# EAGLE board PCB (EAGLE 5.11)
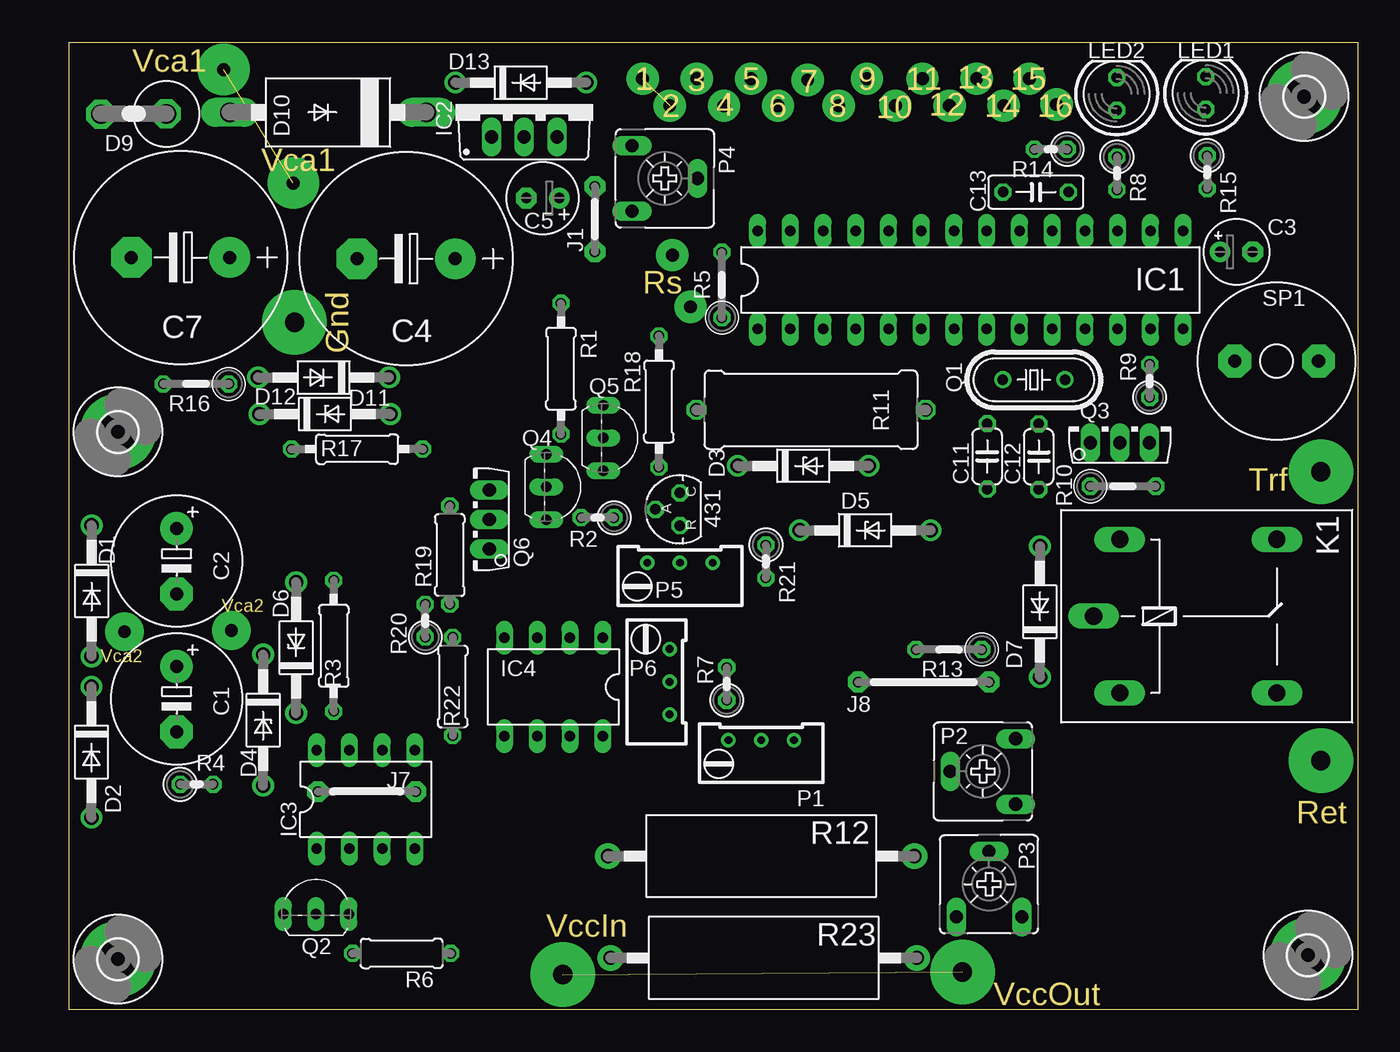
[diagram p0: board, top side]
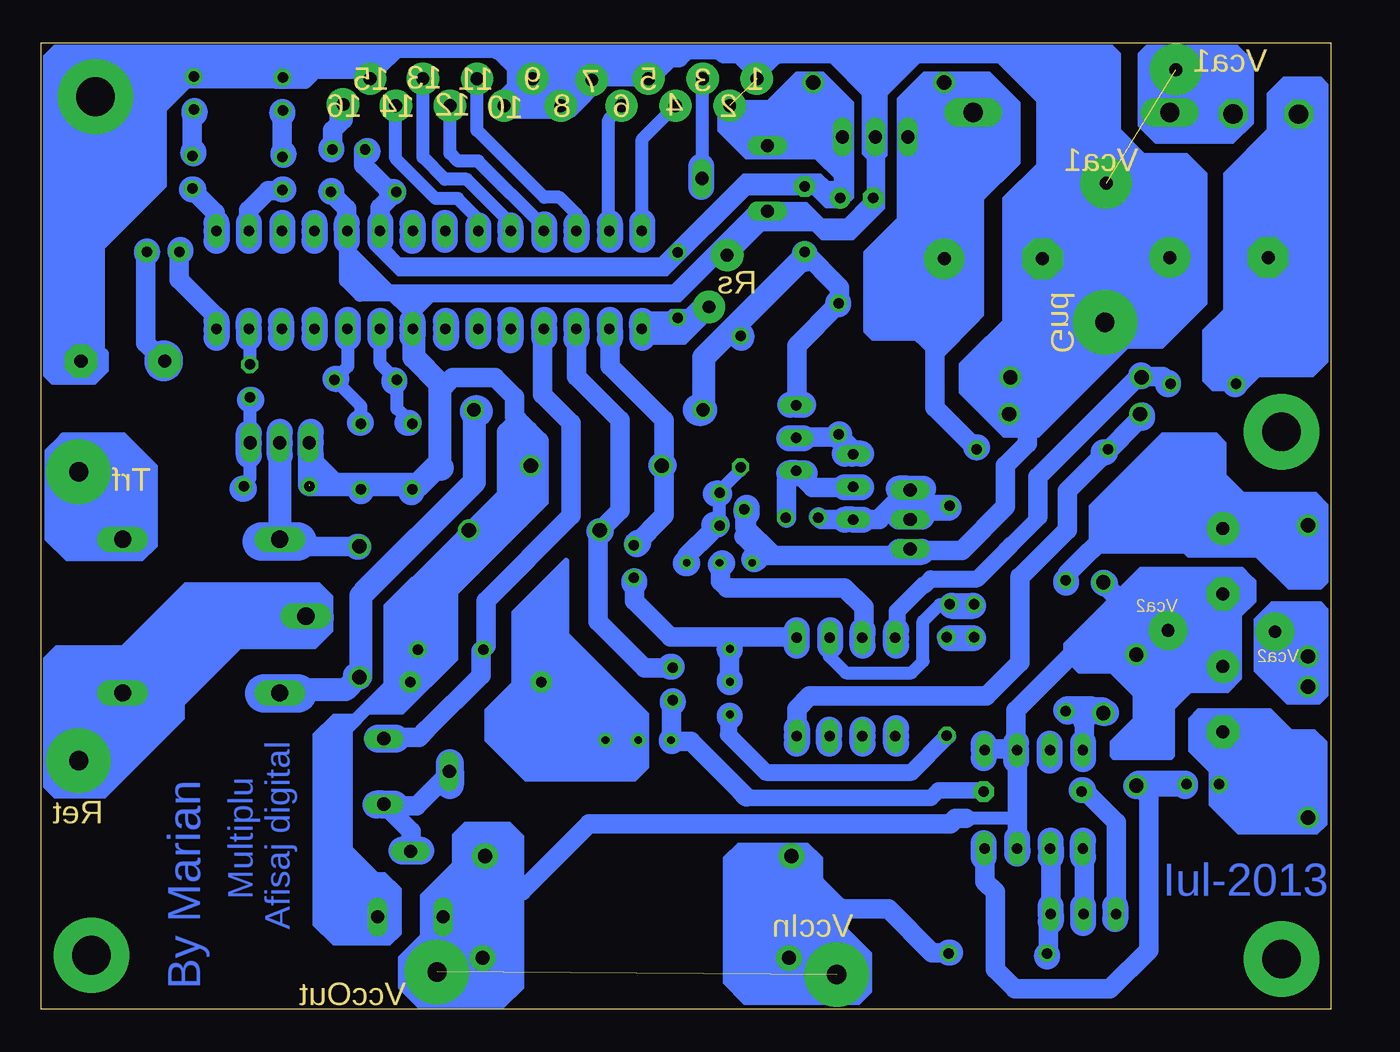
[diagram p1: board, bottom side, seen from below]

Size 100 x 75 mm. Coordinates in mm from the lower left corner, seen from the top.
Outline: 0,0 100,0 100,75 0,75 0,0
Copper layers (1*16): Top 0.035mm / dielectric 1.5mm / Bottom 0.035mm
Design rules "default": minimum track width 10mil, minimum drill 24mil, track to track 8mil, track to pad 8mil, pad to pad 8mil, via to via 8mil, smd to smd 8mil, copper to edge 40mil, drill to drill 8mil, minimum pad ring 10mil, minimum via ring 8mil, stop-mask expansion 4mil, vias tented up to drill 0mil, thermal gap 10mil

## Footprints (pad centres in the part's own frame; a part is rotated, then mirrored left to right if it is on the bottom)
TO92-CLP = drill 0.813 octagon: A 0,1.905; C 1.27,0; R -1.27,0
E5-10,5 = drill 1.016 pad 2.54 round: + -2.54,0 | drill 1.016 pad 2.54 octagon: - 2.54,0
E2,5-5 = drill 0.813 pad 1.6 round: + -1.27,0 | drill 0.813 pad 1.6 octagon: - 1.27,0
E7,5-16 = drill 1.016 pad 3.15 round: + -3.81,0 | drill 1.016 pad 3.15 octagon: - 3.81,0
E2,5-6 = drill 0.813 pad 1.6 round: + -1.27,0 | drill 0.813 pad 1.6 octagon: - 1.27,0
C050-024X044 = drill 0.813 octagon: 1 -2.54,0; 2 2.54,0
C050-025X075 = drill 0.813 octagon: 1 -2.54,0; 2 2.54,0
DO41-10 = drill 1.118 round: A 5.08,0; C -5.08,0
DO41Z10 = drill 1.118 round: A 5.08,0; C -5.08,0
RAD5G = drill 1.499 octagon: A 2.54,0.025; C -2.54,0
C2673 = drill 1.499 long: A 7.62,0; C -7.62,0
3,0-PAD = drill 3 pad 5.842 round: B3,0 0,0
DIL28-3 = drill 0.813 long: 1 -16.51,-3.81; 2 -13.97,-3.81; 3 -11.43,-3.81; 4 -8.89,-3.81; 5 -6.35,-3.81; 6 -3.81,-3.81; 7 -1.27,-3.81; 8 1.27,-3.81; 9 3.81,-3.81; 10 6.35,-3.81; 11 8.89,-3.81; 12 11.43,-3.81; 13 13.97,-3.81; 14 16.51,-3.81; 15 16.51,3.81; 16 13.97,3.81; 17 11.43,3.81; 18 8.89,3.81; 19 6.35,3.81; 20 3.81,3.81; 21 1.27,3.81; 22 -1.27,3.81; 23 -3.81,3.81; 24 -6.35,3.81; 25 -8.89,3.81; 26 -11.43,3.81; 27 -13.97,3.81; 28 -16.51,3.81
TO220BV = drill 1.016 long: D 0,-2.54; G -2.54,-2.54; S 2.54,-2.54
DIL08 = drill 0.813 long: 1 -3.81,-3.81; 2 -1.27,-3.81; 3 1.27,-3.81; 4 3.81,-3.81; 5 3.81,3.81; 6 1.27,3.81; 7 -1.27,3.81; 8 -3.81,3.81
05 = drill 0.813 pad 1.6 octagon: 1 -2.54,0; 2 2.54,0
07 = drill 0.813 pad 1.6 octagon: 1 -3.81,0; 2 3.81,0
10 = drill 0.813 pad 1.6 octagon: 1 -5.08,0; 2 5.08,0
G5LE = drill 1.321 long: 1 -7.493,-5.969; 2 -7.493,5.969; O 4.699,5.969; P -9.525,0; S 4.699,-5.969
LED5MM = drill 0.813 octagon: A -1.27,0; K 1.27,0
RTRIM64W = drill 0.61 round: 1 1.27,-2.54; 2 1.27,0; 3 1.27,2.54
CA6V = drill 1.016 long: A -2.54,-2.54; E 2.54,-2.54; S 0,2.54
HC49/S = drill 0.813 round: 1 -2.413,0; 2 2.413,0
TO92-EBC = drill 0.813 long: B 0,-1.27; C -2.54,-1.27; E 2.54,-1.27
TO126BV = drill 1.016 long: 1 -2.286,-1.27; 2 0,-1.27; 3 2.286,-1.27
0207/10 = drill 0.813 octagon: 1 -5.08,0; 2 5.08,0
0207/2V = drill 0.813 octagon: 1 -1.27,0; 2 1.27,0
0207/5V = drill 0.813 octagon: 1 -2.54,0; 2 2.54,0
0207/7 = drill 0.813 octagon: 1 -3.81,0; 2 3.81,0
0617/17 = drill 1.016 octagon: 1 -8.89,0; 2 8.89,0
RWM6X22 = drill 1.1 pad 2 round: 1 -11.89,0; 2 11.89,0
AL60P = drill 1.016 pad 2.54 octagon: 1 -3.251,0; 2 3.251,0

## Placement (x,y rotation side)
431  [TO92-CLP]  47.39,38.79 90 top
C1  220u  [E5-10,5]  8.34,24.07 270 top
C2  220u  [E5-10,5]  8.34,34.77 270 top
C3  10u  [E2,5-5]  90.55,58.77 0 top
C4  2.2m  [E7,5-16]  26.15,58.23 180 top
C5  47u  [E2,5-6]  36.75,62.93 180 top
C7  2.2m  [E7,5-16]  8.65,58.33 180 top
C11  [C050-024X044]  71.22,42.89 90 top
C12  [C050-024X044]  75.22,42.87 90 top
C13  [C050-025X075]  74.99,63.4 0 top
D1  [DO41-10]  1.76,32.46 270 top
D2  [DO41-10]  1.74,19.96 270 top
D3  [DO41Z10]  56.95,42.16 0 top
D4  [DO41Z10]  15.06,22.45 270 top
D5  5v1  [DO41Z10]  61.75,37.16 0 top
D6  [DO41Z10]  17.62,28.05 90 top
D7  1N4007  [DO41-10]  75.31,30.84 90 top
D9  [RAD5G]  5.01,69.47 180 top
D10  [C2673]  20.09,69.58 180 top
D11  [DO41Z10]  19.85,46.18 0 top
D12  [DO41Z10]  19.75,49.02 180 top
D13  [DO41-10]  35.04,71.89 0 top
E$1  [3,0-PAD]  95.8,70.8 0 top
E$2  [3,0-PAD]  3.8,3.9 0 top
E$3  [3,0-PAD]  96.1,4.2 0 top
E$4  [3,0-PAD]  3.8,44.8 0 top
IC1  PIC16876P  [DIL28-3]  69.92,56.59 0 top
IC2  [TO220BV]  35.31,70.22 0 top
IC3  LM358  [DIL08]  23.02,16.29 0 top
IC4  LM358  [DIL08]  37.58,25.01 180 top
J1  [05]  40.8,61.3 90 top
J7  [07]  23.1,16.9 180 top
J8  [10]  66.3,25.4 0 top
K1  3V  [G5LE]  89,30.5 0 top
LED1  [LED5MM]  88.17,71.08 90 top
LED2  [LED5MM]  81.27,71.02 90 top
P1  5k  [RTRIM64W]  53.69,19.62 90 top
P2  10k  [CA6V]  70.89,18.46 90 top
P3  10k  [CA6V]  71.36,9.71 0 top
P4  10k  [CA6V]  46.21,64.46 270 top
P5  5k  [RTRIM64W]  47.39,33.38 90 top
P6  100k  [RTRIM64W]  45.32,25.41 0 top
Q1  [HC49/S]  74.84,48.84 0 top
Q2  [TO92-EBC]  19.17,8.68 0 top
Q3  [TO126BV]  81.51,45.22 0 top
Q4  [TO92-EBC]  38.3,40.53 270 top
Q5  [TO92-EBC]  42.72,44.33 270 top
Q6  [TO126BV]  31.33,38.01 90 top
R1  1k  [0207/10]  38.16,49.7 270 top
R2  [0207/2V]  41,38.14 180 top
R3  [0207/10]  20.54,28.2 90 top
R4  [0207/2V]  9.9,17.46 0 top
R5  [0207/5V]  50.64,56.2 90 top
R6  100  [0207/7]  25.8,4.34 180 top
R7  470  [0207/2V]  51.02,25.25 90 top
R8  220  [0207/2V]  81.28,64.85 270 top
R9  1k  [0207/2V]  83.82,48.75 90 top
R10  10k  [0207/5V]  81.75,40.58 0 top
R11  [0617/17]  57.56,46.51 180 top
R12  100m  [RWM6X22]  53.69,11.89 0 top
R13  2k2  [0207/5V]  68.25,27.92 180 top
R14  [0207/2V]  76.15,66.72 180 top
R15  220  [0207/2V]  88.28,64.95 270 top
R16  1k  [0207/5V]  9.85,48.52 180 top
R17  [0207/10]  22.35,43.46 0 top
R18  1k  [0207/10]  45.76,47.15 270 top
R19  10k  [0207/7]  29.54,35.25 90 top
R20  [0207/2V]  27.64,30.15 90 top
R21  [0207/2V]  54.06,34.75 270 top
R22  [0207/7]  29.76,25.05 270 top
R23  100m  [RWM6X22]  53.89,3.99 0 top
SP1  [AL60P]  93.67,50.29 0 top

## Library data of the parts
431 = v-reg
C1-C5 C7 C11-C13 P1 P5 P6 R1-R10 R13-R22 = resistor
D1-D7 D9-D13 = diode
E$1-E$4 = holes
IC1 = microchip; OC_FARNELL: unknown; OC_NEWARK: unknown
IC2 Q3 Q6 = transistor-power
IC3 IC4 = ic-package
J1 J7 J8 = jumper
K1 = relay
LED1 LED2 = led
P2-P4 = pot
Q1 = crystal; OC_FARNELL: unknown; OC_NEWARK: unknown
Q2 = transistor-pnp
Q4 Q5 = transistor-npn
R11 = resistor; OC_FARNELL: unknown; OC_NEWARK: unknown
R12 R23 = resistor-power; OC_FARNELL: unknown; OC_NEWARK: unknown
SP1 = buzzer; OC_FARNELL: unknown; OC_NEWARK: unknown

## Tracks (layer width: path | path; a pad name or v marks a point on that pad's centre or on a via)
S$1
  Bottom 0.5: 86.4,60.4 86.4,61.7 88.3,63.6
  Bottom 1.5: 86.5,60.3 86.5,61.8 88.3,63.6 88.4,63.7
  Bottom 2: 88.3,63.6 88.2,63.6
S$2
  Bottom 0.5: 83.8,60.3 83.8,62.2 82.4,63.6 81.3,63.6
  Bottom 2: 81.2,63.6 81.3,63.6
S$3
  Bottom 1.5: 81.3,69.6 81.3,69.8 | 81.3,66.1 81.3,69.5
  Bottom 2: 81.3,69.5 81.3,69.6
S$4
  Bottom 0.5: 88.3,66.3 88.3,66.5 88.3,69.8
  Bottom 1.5: 88.3,66.2 88.3,66.5 88.3,69.7 88.2,69.8
S$5
  Bottom 0.5: 81.3,72.5 88.2,72.5
S$6
  Bottom 0.5: 86.6,52.7 86.6,54.2 89.4,57 89.4,58.8
S$7
  Bottom 0.5: 92,58.7 92,51.9 90.5,50.4 90.4,50.3
  Bottom 3: 90.5,50.2 90.5,50.4
S$8
  Bottom 0.5: 83.9,52.6 83.9,52.1 83.9,49.8
  Bottom 1: 83.8,50.1 83.8,52.7 83.9,52.8
  Bottom 2: 83.9,52.1 83.9,52.8 83.9,53.4
S$9
  Bottom 0.5: 83.7,47.5 83.7,47.3 83.7,43.8 83.8,43.7 83.8,41.2 83.8,41.1 84.5,40.4
  Bottom 1: 84.3,40.4 84.3,40.7 83.8,41.2 83.8,47.3 83.8,47.6
  Bottom 2: 84.3,40.4 84.4,40.4 | 83.8,47.3 83.7,47.3
S$10
  Bottom 0.5: 79.2,43.9 79.2,40.9 78.8,40.5
S$11
  Bottom 0.5: 75.1,40.3 71.3,40.3 71.2,40.4
S$12
  Bottom 0.5: 75.2,46.8 77.2,48.8 | 76.2,51.9 76.2,52.1
  Bottom 1: 75.2,45.4 75.2,45.5 75.2,46.8 77.3,48.9 77.2,48.9 76.2,49.9 76.2,51.9
  Bottom 2: 76.2,52.1 76.2,53.5 | 75.2,45.5 75.3,45.5 | 77.2,48.9 77.1,48.9
S$13
  Bottom 0.5: 73.8,52.7 73.8,50.2 73.7,50.1
  Bottom 1: 71.2,45.4 72.4,46.6 72.4,48.8 73.7,50.1 73.7,51.7
S$14
  Bottom 0.5: 77.6,29.5 77.6,29.4 78.8,28.2 84.6,28.2 89.1,23.7 89.1,22.6 91.2,20.5 | 91.2,20.5 91.2,25.2 91.8,25.8 98.7,25.8 99.6,24.9 | 91.2,20.5 95.1,16.6 98.9,16.6 99.6,17.3 99.6,23.8 99.6,24.9 | 77.6,29.5 78.5,29.5 | 77.6,29.5 77.6,32 78.5,32.9 88.8,32.9 93.7,28 98.8,28 99.6,27.2 99.6,24.9
S$15
  Bottom 0.5: 81.5,43.9 81.5,44 | 81.5,43 81.5,36.5 81.6,36.4 | 75.3,36 81.1,36 81.5,36.4 81.6,36.5
  Bottom 1.5: 75.4,35.9 75.3,35.9 | 75.5,35.9 81.1,35.9 81.5,36.3 81.6,36.4
  Bottom 1.778: 81.5,43 81.5,36.4 | 81.5,43.9 81.5,44.6
  Bottom 2: 81.5,43 81.5,43.9 81.5,44.8 | 75.5,35.9 75.4,35.9
  Bottom 3: 80.1,36.3 81.5,36.3 82.9,36.3
S$16
  Bottom 0.5: 79.2,30.5 79.5,30.5 87.7,30.5 93.8,24.4
  Bottom 2.5: 79.5,30.5 87.2,30.5 93.3,24.4
S$17  (via drill 1.5 pad 5)
  other vias: 97.1,41.7
S$18  (via drill 1.5 pad 5)
  other vias: 97.1,19.3
S$19
  Bottom 0.5: 97,19.5 97,21.3 93.5,24.8
S$20
  Bottom 0.5: 96.9,41.6 96.9,39.8 93.7,36.6
S$21
  Bottom 1: 70.7,21.1 73.3,21.1 | 70.1,21.7 65.8,26 65.8,28
  Bottom 1.5: 61.1,52.8 61.1,47.7 58.9,45.5 58.9,38.3 65.5,31.7 65.5,28.2 65.9,27.8 65.9,25.9 70.1,21.7 70.7,21.1 73.5,21.1
S$22
  Bottom 0.5: 80.1,24.5 76.6,24.5 75.3,25.8
  Bottom 3: 80.1,24.5 81.5,24.5 82.7,24.5
S$23
  Bottom 0.5: 71.2,33.3 73.2,31.3 73.2,25.2 75.7,22.7 77.3,22.7 78.7,21.3 78.7,6.6 77.3,5.2 73,5.2 72.3,5.9 72.3,9.3 73.4,10.4 74,10.4 76.1,12.5 76.1,21.6 74.6,23.1 72,23.1 67.9,27.2 67.9,32.3 60.9,39.3 60.9,42.8 61,42.9 63.8,42.9 64.4,42.3 64.4,39.9
S$24
  Bottom 0.5: 73.7,60.4 73.7,62.1
S$25  (via drill 1 pad 2.5)
  other vias: 74.5,72.2
S$26  (via drill 1 pad 2.5)
  Bottom 0.5: 77.4,68.2 77.4,69.4 v76.6,70.2
  Bottom 1.5: v76.6,70.2 76.6,69 77.4,68.2 77.4,66.7
S$27
  Bottom 1: 48.8,46.5 48.8,50.7 45.7,53.8 | 45.7,53.8 45.7,52.3 45.7,52.2 | 45.7,53.8 40.8,58.7
  Bottom 2: 45.7,52.3 45.7,52.1
  Bottom 2.5: 49,46.5 48.8,46.5
S$28  (via drill 1 pad 2.5)
  other vias: 70.4,72.2
S$29  (via drill 1 pad 2.5)
  Bottom 1: v68.3,70.1 68.3,66.4 67.7,65.8 66.1,65.8 61,60.7
S$30  (via drill 1 pad 2.5)
  other vias: 66.2,72.2
S$31  (via drill 1 pad 2.5)
  other vias: 64.1,70.1
S$32  (via drill 1 pad 2.5)
  Bottom 1: 64.1,70.2 63.9,70.2 v61.9,72.2
S$33  (via drill 1 pad 2.5)
  Bottom 1: v59.7,70.1 59.3,70.1 v57.3,72.1 57.2,72.2 | 52.9,72.3 57.1,72.3 57.2,72.2 | 57.2,72.2 57.2,74.2
S$34
  Bottom 1.5: 83.9,60.4 83.9,62 82.4,63.5 81.3,63.5
S$35  (via drill 1 pad 2.5)
  other vias: 55,70.1
S$36
  Bottom 0.5: 59.3,32.1 59.3,32.7 59.3,34.8 63.3,30.8 63.3,25.3 65.4,23.2 65.4,20.9 62.4,17.9 54,17.9 53.1,18.8 53.1,22.9 59.3,29.1 59.3,32.1
S$37  (via drill 1 pad 2.5)
  Bottom 1: 53.4,60.2 53.4,60.4 53.4,61.1 53.4,67.5 v50.8,70.1
  Bottom 2: 53.4,59.7 53.4,60.4 53.4,61.1
S$38  (via drill 1 pad 2.5)
  Bottom 1: v48.7,72.2 48.7,64.4 48.8,64.3
S$39
  Bottom 2: 78.8,59.6 78.8,60.4 78.8,61
S$40
  Bottom 0.5: 73.7,60.4 73.7,60.3 | 73.7,61.1 73.7,62.1 72.4,63.4 | 74.9,66.7 74.9,65.8 72.5,63.4
  Bottom 1.5: 73.7,61.1 73.7,62.2 72.5,63.4 72.7,63.4 | 72.8,63.4 72.9,63.4 75,65.5 75,66.7 74.8,66.7
  Bottom 2: 73.7,59.6 73.7,60.4 73.7,61.1 | 72.7,63.4 72.8,63.4
S$41  (via drill 1 pad 2.5)
  other vias: 72.5,70.1
S$42  (via drill 1 pad 2.5)
  other vias: 48.2,54.5
S$43
  Bottom 1: 70.4,72.3 70.4,66.1 68.7,64.4 67,64.4 63.6,61
S$44
  Bottom 1: 66.2,72.1 66.2,68.2 61,63 59.8,63 58.5,61.7 58.5,60.9 58.5,60.4
  Bottom 2: 58.5,59.7 58.5,60.4 58.5,60.9
S$45
  Bottom 1: 56,60.4 56,69 55,70
S$46
  Bottom 1: 74.4,72.2 74.4,74.2
S$47
  Bottom 2: 81.3,59.6 81.3,60.4 81.3,61
S$48
  Bottom 2: 83.9,59.6 83.9,60.4 83.9,61
S$49
  Bottom 2: 86.4,59.6 86.4,60.4 86.4,61
S$50
  Bottom 2: 71.2,59.6 71.2,60.4 71.2,61
S$51
  Bottom 2: 68.7,59.7 68.7,60.4 68.7,61
S$52
  Bottom 1: 72.5,70.2 72.5,66 69.4,62.9 67.7,62.9 66.1,61.3 66.1,60.8 66.1,60.4
  Bottom 2: 66.1,59.7 66.1,60.3 66.1,60.8
S$53
  Bottom 2: 63.6,59.7 63.6,60.4 63.6,60.8
S$54
  Bottom 2: 61,59.7 61,60.3 61,60.9
S$55
  Bottom 2: 55.9,59.7 55.9,60.4 55.9,61
S$56
  Bottom 2: 86.4,52.1 86.4,52.7 86.4,53.4
S$57
  Bottom 2: 81.4,52.1 81.4,52.8 81.4,53.4
S$58
  Bottom 2: 78.8,52.1 78.8,52.8 78.8,53.5
S$59
  Bottom 2: 73.7,52.1 73.7,52.8 73.7,53.4
S$60
  Bottom 2: 68.6,52.1 68.6,52.8 68.6,53.4
S$61
  Bottom 2: 66.1,52.2 66.1,52.8 66.1,53.4
S$62
  Bottom 2: 63.6,51.9 63.6,52.8 63.6,53.5
S$63
  Bottom 1: 61,52.8 61,47.7 58.8,45.5 58.8,38.3 65.6,31.5 65.6,28.1 65.7,28
  Bottom 2: 61,52.1 61,52.8 61,53.5
S$64
  Bottom 1: 51,26.5 51.1,26.5 53,26.5 57,30.5 57,36.9 56.6,37.3
  Bottom 1.5: 58.5,52.8 58.5,49.1 55.1,45.7 55.1,38.7 56.7,37.1 56.8,37 56.8,30.1 53.2,26.5 51.1,26.5
  Bottom 2: 58.5,52 58.5,52.8 58.5,53.4 | 56.7,37.1 56.6,37.1
S$65
  Bottom 1: 51.7,42.2 51.7,42.1 | 51.7,45.7 55.8,49.8 55.8,52.8 | 51.8,42.1 51.8,38.2 54,36 54.1,35.9
  Bottom 1.5: 55.9,52.7 55.9,49.9 51.7,45.7 51.7,42.2 51.7,38.3 54,36
  Bottom 2: 55.9,52 55.9,52.7 55.9,53.5 | 51.9,42.2 51.7,42.2
S$66
  Bottom 1: 53.4,52.8 51.5,52.8 50.6,53.7 | 53.4,52.9 53.1,52.9 52.7,53.3 50.1,53.3 48.7,54.7 48.4,54.7 48.1,54.4 48.2,54.4 50.2,52.4 52.2,52.4 52.3,52.3
  Bottom 2: 53.4,52.1 53.4,52.8 53.4,52.9 53.4,53.4
S$67  (via drill 1 pad 2.5)
  other vias: 46.8,58.5
S$68
  Bottom 1: 38,62.9 38,69.8 40.2,72 | 38,62.9 38.5,62.9 39.6,64 45.3,64 51.7,57.6 72.2,57.6 73.8,59.2 73.8,60.5 | 38.7,63.4 38.5,63.4 38,62.9 | 38,62.9 37.7,63.2 37.7,70.2 39.4,71.9 41.2,71.9 43.3,69.8 46.5,69.8 46.7,69.6 46.7,68.5 45,66.8 39.9,66.8 38.4,65.3 38.4,69.2 40.3,71.1 41,71.1 41,70.9 43,68.9 46,68.9 46.1,69 46.1,68.9 44.7,67.5 39.2,67.5 39.1,67.6 39.1,68.9 40.7,70.5 40.7,70.1 42.7,68.1 44.2,68.1 44.4,68.3
S$69
  Bottom 1: 32.8,67.6 32.8,69 29.9,71.9
S$70
  Bottom 1: 43.7,61.8 40.7,61.8 39.7,60.8 37.5,60.8 35.4,62.9
S$71  (via drill 1 pad 4)  (1 unrouted)
  other vias: 17.4,64.1 12,72.9
S$72
  Bottom 1: 4.8,58.3 4.8,65.3
S$73
  Bottom 1: 4.9,58.4 4.9,66.7 2.2,69.4
S$74
  Bottom 1: 12.3,58.1 12.3,58.9 17.5,64.1 | 17.5,64.1 17.6,64.2 | 22.4,58.1 22.4,59.2 17.5,64.1 | 17.5,50.8 17.5,64.1
S$75
  Bottom 0.5: 38.2,63.8 38.2,64
S$76
  Bottom 1: 30,58.2 30,62.2 | 30,62.2 30,62.5 26.1,66.4 26.1,68.9 26,69 | 32.9,67.7 32.9,65.1 30,62.2
S$77
  Bottom 1: 4.9,58.2 4.9,51 7.1,48.8
S$78
  Bottom 1.5: 12.4,48.5 13,49.1 14.7,49.1 14.9,49.1 22.7,41.3 22.7,38.3
  Bottom 2: 14.7,49.1 14.7,49.2
S$79
  Bottom 0.5: 25.7,73.6 22.6,70.5 22.6,65.5 25.2,62.9 25.2,52
S$80
  Bottom 1: 34.7,53.4 34.6,53.4 29.6,58.4
S$81
  Bottom 1: 38.3,54.8 38.3,56.4 40.7,58.8
S$82
  Bottom 1: 41.4,44.3 41.5,44.3 | 40.9,44.3 38.5,44.3 38.2,44.6
  Bottom 1.5: 37,43 37,43.4 38.2,44.6 38.2,44.5 38.3,44.4
  Bottom 2: 42,44.3 41.4,44.3 40.9,44.3 | 38.2,44.5 38.1,44.6
S$83
  Bottom 1: 41.4,46.9 41.4,47
  Bottom 1.5: 41.4,47 41.4,51.5 38.2,54.7 38.1,54.8 38.1,56 40.9,58.8
  Bottom 2: 40.9,46.9 41.4,46.9 41.9,46.9 | 38.2,54.7 38.2,54.8
S$84
  Bottom 1: 37.1,42.9 37.1,43.1 37.1,43.3 38.2,44.4
  Bottom 1.5: 38.2,44.4 41.3,44.4
  Bottom 2: 36.4,43.1 37.1,43.1 37.7,43.1
S$85
  Bottom 1: 37.1,40.6 40.2,40.6 41.5,41.9
S$86
  Bottom 1: 36.9,38.1 39.8,38.1
S$87
  Bottom 1: 42.4,38.1 42.4,40.8 41.5,41.7
  Bottom 1.5: 42.2,38.1 42.2,41 41.5,41.7
S$88
  Bottom 1: 38.9,28.8 38.9,27.4 37.6,26.1 32.5,26.1 31.6,27 31.6,30.1 30.3,31.4 29.6,31.4 29.4,31.4 27.6,31.4
S$89
  Bottom 1: 41.4,28.8 51.3,28.8 54,31.5 54,31.7
  Bottom 1.5: 41.4,28.9 51.2,28.9 54,31.7 54,33.1 | 54,33.2 54,33.4
  Bottom 2: 41.4,28.2 41.4,28.8 41.4,28.9 41.4,29.4 | 54,33.1 54,33.2
S$90
  Bottom 1: 45.8,42 45.8,41.8 47.4,40.2 47.4,40 47.4,37.6 | 47.4,37.6 47.4,37.4 | 49.9,34.6 49.9,35.1 47.4,37.6
  Bottom 2: 47.4,40 47.7,40
S$91
  Bottom 1.778: 40.8,58.6 40.8,58.4 48.6,50.6 48.6,46.6
  Bottom 2: 40.8,58.6 40.8,58.2
S$92
  Bottom 1: 41.4,4.4 42.1,3.7
S$93
  Bottom 1: 75.3,25.7 75.3,32.6 66.6,41.3 66.6,46.4 66.5,46.5
  Bottom 1.778: 66.4,46.5 66.4,40.9 75.2,32.1 75.2,25.8 75.3,25.7 75.5,25.7 76.4,24.8 81.2,24.8 81.3,24.7
S$94
  Bottom 1.5: 33.6,28.5 33.5,28.4
S$95
  Bottom 1.3: 46.7,22.9 46.7,21.3 43.8,18.4 32.5,18.4 29.7,21.2
S$96
  Bottom 1: 33.7,28.8 33.8,28.8
  Bottom 2: 33.7,29.4 33.7,28.8 33.7,28.2
S$97
  Bottom 2: 26.9,11.8 26.9,12.9
S$98
  Bottom 0.5: 41.1,0.6 41.6,0.6 45.4,0.6 46.9,2.1 46.9,11.7 45.9,12.7 40.6,12.7 39.6,11.7 39.6,8.1 35.8,4.3 35.8,1.4 36.6,0.6 41.1,0.6
S$99
  Bottom 1: 63.9,41.9 62.2,41.9 61.9,42.2
S$100
  Bottom 1: 46.6,25.5 46.6,28.1 46.7,28.2
S$101
  Bottom 1: 22.6,38.3 22.6,41.1
S$102  (1 unrouted)
  Bottom 0.5: 71.2,54.1 71.2,53.4 | 72.5,55.4 75.2,55.4 76.4,56.6 76.4,59.5 76.4,60.3 76.3,60.4
  Bottom 1: 43.7,62 44.3,62 50.9,55.4 72.5,55.4 | 71.2,52.8 71.2,54.1 72.5,55.4 | 72.5,55.4 75.3,55.4 76.4,56.5 76.4,59.5 | 71.2,52.7 71.2,50.7 71.1,50.6 68.8,48.3 68.8,42 70.5,40.3 71.3,40.3 78.9,40.3 79.2,40.6
  Bottom 1.5: 77.5,63.4 77.5,63.3 76.3,62.1 76.3,61 | 76.3,60.4 76.3,60.3
  Bottom 1.778: 79.2,40.7 79.2,44.7 | 79.2,44.1 79.2,42.6 77.3,40.7 70.8,40.7 69.4,42.1 69.2,42.1 69.1,42.2 69.1,48.6 71.1,50.6 71.1,52
  Bottom 2: 76.3,59.6 76.3,60.4 76.3,61 | 71.2,52.2 71.2,52.7 71.2,52.8 71.2,53.4 | 71.3,40.3 71.3,40.1 | 77.5,63.4 77.5,63.5
S$103
  Bottom 1.5: 86.5,52.7 86.5,53.8 89.3,56.6 89.3,58.9
S$104
  Bottom 1: 46.6,22.8 46.6,22.9
  Bottom 1.5: 46.6,22.8 46.6,23
  Bottom 2: 46.6,22.8 46.6,22.7
S$105
  Bottom 1: 10.9,68.9 10.2,69.6
S$106
  Bottom 1: 7.3,69.4 12.7,69.4
S$107
  Bottom 1: 12,72.7 12,69.9 12.4,69.5
S$108  (via drill 1 pad 3)
  other vias: 4.3,29.3
S$109
  Bottom 1: 1.7,37.5 8.3,37.5
S$110
  Bottom 1: 8.5,26.6 8.5,32.1 8.3,32.3
S$111
  Bottom 1: 1.6,25 1.6,27.4 1.8,27.6 2.5,27.6 4.3,29.4
S$112
  Bottom 1: 1.8,14.7 1.8,18.3 4.8,21.3 8.4,21.3 8.6,21.5
S$113  (via drill 1 pad 3)
  Bottom 1: 8.6,29.4 v12.6,29.4
S$114
  Bottom 1: 8.3,37.3 8.7,37.3 11.7,40.3
S$115
  Bottom 0.5: 6.4,33.6 6,33.2 6,31.7 7.1,30.6 7.1,28.6 | 12.3,21.1 12.3,23.4 10.9,24.8 8,24.8 7.1,25.7 7.1,28.6 | 12.3,20.9 12.3,21.1 | 7.1,28.6 7.3,28.6 | 6.4,33.6 6.4,32.9 | 6.4,33.6 6.9,34.1 14.7,34.1 20.5,28.3 20.5,27.3 19.5,26.3 17,26.3 15.1,24.4 15.1,22.5 | 15.1,22.5 15.1,21 13.7,19.6 13.6,19.6 12.3,20.9 | 12.3,21.1 12.9,21.1 | 12.3,20.9 12.3,19.7 12.4,19.6 16.8,19.6 16.9,19.7 16.9,20.7 15.1,22.5
S$116
  Bottom 1: 21.8,7.6 21.8,7.5
S$117
  Bottom 1.5: 46.6,25.5 46.6,27.9 | 46.6,28 46.6,28.6
  Bottom 2: 46.6,25.5 46.6,25.4 | 46.6,27.9 46.6,28
S$118
  Bottom 1: 41.8,11.8 41.8,3.9 41.9,3.8
S$119
  Bottom 1: 65.8,11.7 65.8,4 66,3.8
S$120
  Bottom 1: 47.4,34.6 47.4,33.3 47.3,33.2 46.7,32.6 43.4,32.6
  Bottom 1.5: 47.4,34.6 47.3,34.5 47.3,33.2 46.8,32.7 37.7,32.7 36.2,31.2 36.2,29.3 36.3,29.2
  Bottom 2: 36.3,28.2 36.3,29.2 36.3,29.4 | 47.2,34.6 47.3,34.5
S$121
  Bottom 1: 11.2,17.4 11.4,17.6
  Bottom 1.5: 11.3,17.5 11.2,17.4
S$122
  Bottom 1.5: 21.9,7.5 21.9,4.5 22.1,4.3
S$123
  Bottom 1.5: 29.7,4.4 30.9,4.4 34.3,7.8 41.6,7.8 41.7,7.9
S$124
  Bottom 1.5: 49.9,34.5 49.9,34.6 49.9,35.2 48.1,37
  Bottom 2: 49.9,34.6 50,34.6
S$125
  Bottom 1: 19.2,20.7 19.2,22.3 19.2,23.6
  Bottom 1.5: 17.6,22.9 18.6,22.9 19.2,22.3
  Bottom 2: 19.2,20.7 19.2,19.4
S$126
  Bottom 1: 12.7,29.4 15.3,29.4
S$127
  Bottom 2: 19.2,11.8 19.2,13.1
S$128
  Bottom 1: 19.1,7.7 19.2,7.8
S$129
  Bottom 2: 16.7,8 16.7,7
S$130
  Bottom 2: 31.7,38.2 33.4,38.2
S$131
  Bottom 1: 19.2,7.5 19.2,7.6
  Bottom 1.5: 19.2,6.7 19.2,6.5
  Bottom 2: 19.2,6.7 19.2,7.5 19.2,8
S$132
  Bottom 1: 65.6,8.1 65.5,8 64,8 57.5,14.5 38.8,14.5
S$133
  Bottom 1: 58.6,52.8 58.6,49.4 55,45.8 55,38.8 56.6,37.2
S$134  (via drill 1.5 pad 5)  (1 unrouted)
  other vias: 69.3,2.9 38.3,2.7
S$135
  Bottom 1: 68.7,7.1 68.7,3.4 69.5,2.6
S$136
  Bottom 1: 65.6,3.9 67.9,3.9 69.2,2.6
S$137
  Bottom 1: 68.9,7.3 68.9,8.5 65.4,12
S$138
  Bottom 1: 68.3,18.5 70.9,15.9 72.6,15.9 | 73.5,15.9 71.3,13.7 71.3,12.2
  Bottom 2.184: 74,15.9 73.5,15.9 72.6,15.9 | 68.3,17.4 68.3,18.5 68.3,19.1
S$139
  Bottom 1: 53.7,20.9 56.9,20.9 61.3,25.3
S$140
  Bottom 1: 63.7,41.8 63.7,40.4 71.2,32.9 71.2,28.3 70.8,27.9 70.8,26.1 71.6,25.3
S$141
  Bottom 1: 71.4,25.4 72.5,25.4 72.7,25.4 77.4,20.7 77.4,10.6 73.8,7
  Bottom 1.5: 72.2,24.9 72.2,25.1 72.5,25.4 72.5,31.1 63.8,39.8 63.8,39 63.9,38.9 63.9,38.3 71.5,30.7 71.5,26.4 | 71.5,26.4 71.7,26.2 | 71.5,26.4 70.2,27.7 70.2,31 69.9,31.3 69.9,31 70.4,30.5 70.4,28.1 70.3,28
S$142
  Bottom 1.5: 91.9,58.8 91.9,51.7 90.5,50.3
S$143  (via drill 1.5 pad 5)
  other vias: 17.5,53.3
S$144
  Bottom 2: 32.8,40.4 31.6,40.4 | 32.8,40.4 33.5,40.4 | 32.8,40.4 32.8,38.5
S$145
  Bottom 0.5: 34.9,66.1 34.8,66.1 34.6,66.3 34.6,71 31.9,73.7 | 34.9,66.1 34.9,66.3 | 34.9,66.1 35.8,66.1 36.1,66.4 36.1,71 38.6,73.5
S$146
  Bottom 0.5: 27,72.3 29.8,72.3 30,72.5 | 30,72.5 28.9,72.5 26.5,72.5 24.3,70.3 24.3,65.7 27.1,62.9 27.1,53.9 28.9,52.1 35.5,52.1 36,52.6 36,58.7 33.4,61.3 33.4,70.6 31.5,72.5 30,72.5
S$147
  Bottom 0.5: 37.2,67.6 37.5,67.6 | 37.2,67.6 37.2,69 | 37.2,69 37.2,70.3 39.4,72.5 41.4,72.5 43.6,70.3 47.4,70.3 47.5,70.2 47.5,69.8 47.3,69.6 47.3,68.2 45.3,66.2 39.9,66.2 38.1,64.4 | 37.2,69 37.5,69 | 37.2,67.6 37.2,63 37.8,62.4 39.1,62.4 40.1,63.4 45.7,63.4 45.8,63.3
S$148
  Bottom 0.5: 39.3,63.3 39,63.3 38.3,64
S$149
  Bottom 0.5: 38.1,64.3 38.4,64 39,64 39.6,64.6 45.5,64.6 52,58.1 72.2,58.1 73.1,59
S$150
  Bottom 0.5: 40.1,63.8 40,63.8 38.8,62.6
S$151
  Bottom 0.5: 45.4,63.6 45.4,63.4 46,62.8
S$152
  Bottom 0.5: 45,63.6 51.5,57.1 72.3,57.1 74.2,59
S$153
  Bottom 0.5: 76,59.6 75.8,59.4 75.8,58.9 72.9,56 | 72.9,56 72.7,55.8 | 72.9,56 51,56 44.8,62.2 43.1,62.2 42.9,62.4 40.7,62.4 39.4,61.1 37.6,61.1 35.9,62.8
S$154
  Bottom 0.5: 76,58.7 76,58.6 73.2,55.8 74.8,55.8 75.7,56.7 75.7,57.8 | 75.7,57.8 75.8,57.9 | 75.7,57.8 74,56.1 74.5,56.1 74.6,56.2 74.7,56.2 75.5,57
S$155
  Bottom 0.5: 70.7,52.9 70.7,54.1 69.8,55
S$156
  Bottom 0.5: 71.6,52.9 71.6,53.9 73.2,55.5
S$157
  Bottom 0.5: 71,54.3 71,54.4 70.1,55.3
S$158
  Bottom 0.5: 71.2,54.4 71.2,55 71,55.2
S$159
  Bottom 0.5: 71,54.6 71,54.7 70.5,55.2
S$160
  Bottom 0.5: 73.6,55.6 70.2,55.6 69.7,55.1 50.5,55.1 44,61.6
S$161
  Bottom 0.5: 45.3,60.6 40.1,60.6 39.4,59.9 37.1,59.9 34.8,62.2 34.8,66.2
S$162
  Bottom 0.5: 48,54.3 48,53.9 50.1,51.8 52.9,51.8
S$163
  Bottom 0.5: 53.3,53.5 53.1,53.5 52.7,53.9 51.3,53.9 51.1,54.1 49.9,54.1 48.9,55.1
S$164
  Bottom 0.5: 98.2,44.5 98.3,44.5 98.5,44.3 99.5,43.3 99.5,36.5 98,35 92.2,35 91.2,36 91.2,42.1 93.6,44.5 98.2,44.5
S$165
  Bottom 2: 30.8,55.2 29.2,55.2 28,56.4 28,63.5 25.3,66.2 25.3,69.7 27,71.4 31,71.4 32.4,70 32.4,60.7 35.1,58 35.1,53 35,52.9 29.5,52.9 28,54.4 28,65.9 27.3,66.6 27.3,69.5 27.4,69.6 30.4,69.6 30.5,69.7 30.5,60.4 33.4,57.5 33.4,54.7 33.5,54.6 30.4,54.6 30.4,55.9 29.6,56.7 29.6,66.1 28.6,67.1 28.6,69.7 29.8,69.7 30,69.9 30,58.9 32.4,56.5
S$166
  Bottom 1: 32.6,74 32.6,73.9 35.1,71.4 35.1,62.4 37.2,60.3 39.4,60.3 40.2,61.1 44.1,61.1 | 44.1,61.1 44.4,61.1 | 44.1,61.1 43.9,61.3 43.9,61.1 46.8,58.2
S$167
  Bottom 1: 40.6,69.8 40.6,69.5 41.8,68.3
S$168
  Bottom 1: 41.5,68.1 39.9,68.1 39.8,68.2 39.8,68.6 40,68.8 40,68.9 40.1,69 40.2,69 40.5,68.7
S$169
  Bottom 1: 37.8,73.7 37.8,73.4 36.1,71.7
S$170
  Bottom 1: 35.1,72.2 35.1,72.4 34.1,73.4
S$171
  Bottom 1: 36.4,73 34.7,73
S$172
  Bottom 1: 44.4,72.3 44.4,72.4 43.1,73.7 | 44.4,72.3 44.4,72.2 | 44.4,72.3 45.9,73.8
S$173  (via drill 1 pad 2.5)  (1 unrouted)
  Bottom 1: 50.7,74.1 50.7,74 52.6,72.1 56.5,72.1 59,69.6 64.5,69.6 64.8,69.9 64.8,70.2 63.4,71.6 63.4,73 64,73.6 | 96.9,50.1 96.9,63 91.4,68.5 91.4,72.7 89.8,74.3 86.3,74.3 | 24.7,73.9 47.2,73.9 47.5,74.2 49.8,74.2 50.4,73.6 64,73.6 | 81.8,71.9 79.5,71.9 78.4,73 73.7,73 72.4,74.3 | 37.8,67.7 38.5,67 43.7,67 | 86.3,74.3 88.2,72.4 | 64,73.6 64.6,74.2 64.7,74.2 64.8,74.3 | 81.3,74.3 86.3,74.3 | 81.3,74.3 81.3,72.4 | 43.7,67 43.6,66.9 | 43.7,67 46.6,69.9 v46.6,70.1 | 72.4,74.3 81.3,74.3 | 64.8,74.3 72.4,74.3 | 61.9,74.3 64.8,74.3 | 61.9,74.3 61.9,72.3 | 52.9,74.3 61.9,74.3 | 52.9,74.3 v52.9,72.2 | v44.5,72.2 44.5,73.2 45.6,74.3 | 45.6,74.3 52.9,74.3 | 35.5,62.9 35.5,72.2 37.6,74.3 | 37.6,74.3 45.6,74.3 | 37.6,74.3 21.5,74.3 19.4,72.2 17.4,70.2 17.4,64.2
  Bottom 2: 18.3,58.2 17.9,58.6 17.9,61.2 16.9,60.2 16.9,60 17,59.9 17,57.7 17.9,56.8 19.7,56.8 19.7,60.7 18.1,62.3 18.1,62.9 16.3,61.1 15.8,61.1 15.4,60.7 15.4,57.2 17.2,55.4 20.3,55.4 21.2,54.5 21.2,53.4 21.3,53.5 21.3,60.9 18.8,63.4 18.7,63.4 19.4,64.1 19.4,65.3 16.5,62.4 14.1,62.4 13.8,62.1 13.8,56.8 16.7,53.9 19.6,53.9 23.5,50 23.5,49.8 22.7,50.6 22.7,61.7 20.3,64.1 20.3,71.4 21.4,72.5 | 21.4,72.5 21.5,72.6 | 21.4,72.5 19.1,72.5 19.4,72.2 19.1,71.9 19.1,66.8 15.8,63.5 12.4,63.5 12.6,63.3 12.6,55.9 16.2,52.3 18.6,52.3 22.6,48.3
S$174
  Bottom 1: 63.7,70 63.3,70 62.3,71 62.3,72.7 62.7,73.1 62.7,70.3 60.2,70.3 58.2,72.3 52.9,72.3 51.9,73.3 52.2,73.3 52.6,72.9 61.6,72.9 61.7,73 61.7,71.2 61.8,71.1 60,71.1 58.9,72.2 61.2,72.2 61.4,72.4 61.4,71.8 61.2,71.6 60.1,71.6
S$175
  Bottom 1: 73.7,73.9 73.7,73 74.1,72.6 74.1,72.4 74.5,72 74.8,72.3 74.8,72.6 74.7,72.7 80.4,72.7 81,72.1 89.1,72.1 91.1,70.1 91.1,64.2 96,59.3 96,51.1 95.6,50.7 95.6,50 96.3,49.3 98.8,49.3 99,49.5 99,73.6 98.6,74 75.5,74 75.1,73.6 79.3,73.6 79.5,73.4 81.7,73.4 82.1,73 82.3,73 82.4,73.1 86.9,73.1 87.4,72.6 89.7,72.6 90.9,71.4 90.9,68.8 91.8,67.9 91.8,64.6 96.4,60 96.7,60 97.6,59.1 97.6,50.4 97.2,50 98.2,50 98.3,50.1 98.3,73.3 87.9,73.3 87.9,73.1 88.2,72.8 90.4,72.8 91,72.2 91.7,72.2 92.3,72.8 92.3,65.3 97.7,59.9 97.7,72.6 93.1,72.6 92.9,72.4 92.9,65.7 96.4,62.2 96.4,62.5 97.1,63.2 97.1,71.9 97,72 93.8,72 93.6,71.8 93.6,67.2 96.5,64.3 96.5,71.3 94.3,71.3 94.2,71.4 94.2,67.7 96.1,65.8 96.1,70.3 95.8,70.6 95,70.6 94.9,70.7 94.9,67.7 95.6,67 95.6,70 95.4,70.2
S$176
  Bottom 0.5: 9.7,48.8 9.7,52.6 8.1,54.2 8.1,64.8 4.7,68.2 4.7,71 3.6,72.1 0.8,72.1 0.4,71.7 0.4,50.3 1.4,49.3 5.6,49.3 6.7,48.2 9.1,48.2 9.7,48.8
S$177
  Bottom 0.5: 11.8,73.9 11.8,74.7
S$178
  Bottom 0.5: 12.1,74.6 12.1,73.9 | 12.1,74.6 10.7,74.6 7.3,74.6 6.2,73.5 6.2,68.8 7.6,67.4 13.5,67.4 14.7,68.6 14.7,74.1 14.2,74.6 12.1,74.6
S$179
  Bottom 1.422: 2.2,70.3 1.1,71.4 1.1,50.6 1.7,50 6,50 7.1,48.9 8.6,48.9 8.9,49.2 8.9,52.2 7.4,53.7 7.4,64.4 4.1,67.7 4.1,70.7 3.4,71.4 1.5,71.4 1.5,51.8 2.2,51.1 6.3,51.1 7.4,50 7.9,50 7.9,51.8 6.3,53.4 6.3,64.2 3,67.5 3,70.1 2.8,70.3 2.3,70.3 2.2,70.2 2.2,52.7 2.7,52.2 6.5,52.2 7.2,51.5 6.3,51.5 5.1,52.7 5.1,64 3,66.1 3,53.3 2.9,53.2 4,53.2 4.2,53.4 4.2,63.8 3.7,64.3
S$180
  Bottom 1.422: 12.7,73 12.7,73.8 7.6,73.8 7,73.2 7,69 7.8,68.2 13.3,68.2 13.9,68.8 13.9,73.8 13.8,73.9 8.9,73.9 8.2,73.2 8.2,70.4 8.1,70.3 12.2,70.3 13.1,69.4 13.1,72.4 12.6,72.9 9.4,72.9 9.3,72.8 9.3,71.5 9.6,71.2 11.2,71.2 11.3,71.1 11.3,71.9 10.2,71.9
S$181
  Bottom 1: 17.8,43.2 20.6,40.4 20.6,37.4 24.3,33.7 24.3,27 26.8,24.5 40.2,24.5 41.4,23.3 41.5,23.2 41.5,21.2
  Bottom 1.5: 17.7,42.9 17.7,43.4 | 17.7,42.9 17.8,42.8 20.4,40.2 20.4,37.2 24.1,33.5 24.1,26.9 26.7,24.3 40.4,24.3 41.4,23.3 41.4,21.8 | 41.4,21.2 41.4,20.7 | 14.7,46.1 14.7,45.9 17.7,42.9
  Bottom 2: 41.4,20.6 41.4,21.2 41.4,21.8
S$182
  Bottom 1: 44.9,34.7 44.8,34.7 43.6,35.9 44.6,35.9 44.8,35.9 45.5,36.6 45.5,36.7 45.5,38.8
  Bottom 1.5: 45.4,38.8 45.3,38.7 45.3,38.5 45.3,36.9 45.5,36.7 44.2,35.4 | 45.4,38.8 45.5,38.9 | 44.2,35.4 44.6,35 | 44.7,34.9 44.8,34.8 | 43.8,35.8 44.2,35.4 | 43.9,35.2 44.6,35.9 44.5,35.9 43.8,35.2 33.6,35.2 33.3,35.5 | 45.4,38.8 45.4,37.4 43.3,35.3
  Bottom 2: 45.3,38.5 45.3,38.9 | 33.4,35.5 33.3,35.5 31.7,35.5 | 44.7,34.9 44.6,35
S$183
  Bottom 1.5: 39.7,38.2 39.5,38 37.7,38 | 35.1,38 35,38 34.1,38.9 | 37,38 35.1,38 | 35.1,38 33.6,39.5
  Bottom 2: 36.3,38 37,38 37.7,38
S$184
  Bottom 1.5: 37.7,40.5 40.2,40.5 41.5,41.8
  Bottom 2: 36.4,40.5 37.7,40.5
S$185
  Bottom 1.5: 27.5,43.5 30.7,46.7 30.7,49.8 30.7,51 | 30.7,51 27.8,53.9 | 30.7,51 30.7,51.4 32.4,53.1
S$186
  Bottom 2: 7.2,32.9 7.1,32.8 7.1,32 8.1,31 8.1,26 8.4,25.7 11.4,25.7 12.5,24.6 13.7,24.6
S$187
  Bottom 2: 21.8,19.3 21.8,20.1 21.8,20.6
S$188
  Bottom 3: 78.8,30.4 79.5,30.4 80.6,30.4
S$189
  Bottom 0.5: 64.2,0.3 62.8,1.7 62.8,13.4 63.7,14.3 67.1,14.3 67.9,13.5 67.9,11.3 70.4,8.8 70.4,5.7 72.1,4 72.1,1.7 70.7,0.3 64.2,0.3
S$190
  Bottom 2: 26.9,19.5 26.9,20.2 26.9,20.6
S$191
  Bottom 1.27: 27,17 30.4,17 31,16.4 45.4,16.4 45.9,16.9
S$192
  Bottom 1.27: 44.1,35.9 44.2,35.8
S$193
  Bottom 1.5: 8.4,17.4 8.5,17.5 8.5,21.3 8.3,21.5
S$194
  Bottom 1.5: 71.3,12.1 71.3,12.3 71.3,13.8 73.3,15.8 70.9,15.8 68.3,18.4
  Bottom 2.184: 72,12.3 71.3,12.3 70.6,12.3
S$195
  Bottom 0.5: 7.3,40.4 6.8,39.9 1.2,39.9 0.4,39.1 0.4,33.2 0.8,32.8 3.2,32.8 5.7,35.3 11,35.3 12.1,36.4 12.1,41.1 11.8,41.4 8.3,41.4 | 7.3,39.5 7.3,40.4 | 7.3,40.4 8.3,41.4 | 8.3,41.4 8.3,43.9 8.9,44.5 13,44.5 18.5,39 18.5,36.1
S$196
  Bottom 0.5: 1.5,31.4 2.2,31.4 4.5,31.4 5.7,30.2 5.7,26.3 3.3,23.9 0.9,23.9 0.4,24.4 0.4,31 0.8,31.4 1.5,31.4
S$197
  Bottom 0.5: 0.5,17 0.5,17.1 0.5,20.7 1.3,21.5 3.1,21.5 4.7,23.1 10.2,23.1 10.8,22.5 10.8,20.1 9.2,18.5 9.2,15.9 7.1,13.8 1.1,13.8 0.5,14.4 0.5,17
S$198
  Bottom 2.184: 73.9,21 73.4,21 72.5,21
S$199
  Bottom 1.5: 19.1,7.4 19.1,12.4
S$200
  Bottom 2: 3.2,37.4 1.4,37.4 1.4,33.7 2.5,33.7 5.1,36.3 10.5,36.3 11.1,36.9 11.1,40.3 11.2,40.4 8.8,40.4 7.4,39 1.8,39 1.4,38.6 1.4,34.9 1.5,34.8 1.6,34.8 3.7,36.9 9,36.9 9.8,37.7 9.8,39 9.9,39.1 8.9,39.1 7.9,38.1
S$201
  Bottom 2: 1.9,29.2 1.9,29.9 1.3,30.5 1.3,25.1 1.6,24.8 2.7,24.8 3,25.1 3.1,25.1 4.7,26.7 4.7,30 4.2,30.5 2.4,30.5 2.3,30.6 2.3,26.4 2.1,26.2 2.9,26.2 3.4,26.7 3.4,29.2 3.3,29.3
S$202
  Bottom 2: 2.7,17.8 1.6,17.8 1.5,17.7 1.5,14.9 1.6,14.8 6.7,14.8 8.3,16.4 8.3,19.1 9.7,20.5 9.7,22.1 9.6,22.2 5.2,22.2 3.7,20.7 1.8,20.7 1.4,20.3 1.4,17.1 2.3,16.2 6.4,16.2 6.7,16.5 6.7,19.8 7.2,20.3 5.3,20.3 5.2,20.4 3.3,20.4 2.5,19.6 2.9,19.6 3.7,18.8 3.7,17.8 3.8,17.7 4.9,17.7 5.1,17.5 5.1,18.9 5.2,19
S$203
  Bottom 2: 9.4,31.4 9.5,31.3 9.5,27.2 9.6,27.1 11.6,27.1 13.4,25.3 13.4,21.2 13.7,20.9
S$204
  Bottom 2: 43.6,7.8 43.6,10.2 42.2,11.6 40.9,11.6 40.5,11.2 40.5,7.5 36.8,3.8 36.8,1.7 37,1.5 44.9,1.5 46,2.6 46,11.1 45.4,11.7 43.2,11.7 43.1,11.6 43.1,10.4 42.6,9.9 42.6,7.4 38.3,3.1 43.9,3.1 44.2,3.4 44.2,10.2 44.3,10.3 44.3,7.4 42.8,5.9 42.8,4.5 42.7,4.4 40.7,4.4
S$205
  Bottom 2: 64.4,1.5 69.1,1.5 | 64,1.9 64.4,1.5 | 64,1.9 63.8,2.1 63.8,13.1 64.1,13.4 66.5,13.4 66.9,13 66.9,10.8 69.4,8.3 69.4,5.2 71.1,3.5 71.1,2 70.3,1.2 64.7,1.2 64.4,1.5 | 64,1.9 64.9,1.9 65,2 65,11.9 65.1,12 65.9,12 65.9,9.4 68,7.3 68,4.3 69.8,2.5 67.1,2.5 66.7,2.9 66.7,7.3 66.6,7.4
S$206
  Bottom 2: 76.4,7.3 73.5,7.3 73.4,7.4 73.4,8.9 73.8,9.3 74.5,9.3 77.1,11.9 77.1,21.6 76.9,21.8 77,21.8 77.8,21 77.8,7.1 76.9,6.2 73.3,6.2 73.2,6.3 73.9,6.3 76.8,9.2
S$207
  Bottom 2: 98,18.6 94.5,18.6 90,23.1 90,24.3 85.2,29.1 79.4,29.1 78.6,29.9 78.6,31.7 78.7,31.8 88.5,31.8 93.7,26.6 93.7,26.9 93.8,27 98.3,27 98.7,26.6 98.7,17.8 98.5,17.6 95.5,17.6 95.3,17.8 95.3,19.6 94.7,20.2 94.7,20.9 91.8,23.8 91.8,24.4 87.1,29.1
S$208
  Bottom 2: 97.8,20 97.2,20 94.2,23 94.2,24.8 94,25 97.1,25 97.3,25.2 97.3,21.6 97.4,21.5 97.4,22 95.4,24
S$209
  Bottom 2: 96,38.5 92.4,38.5 92.2,38.7 92.2,41.6 94,43.4 97.9,43.4 98.5,42.8 98.5,36.7 97.7,35.9 92.8,35.9 92.2,36.5 92.2,39.9 94,41.7 97.1,41.7 97.2,41.6 97.2,37.4 97,37.2 93.4,37.2 93.4,39.9 93.9,40.4 95.6,40.4 95.6,40.1 96.1,39.6 | 96.1,39.6 94.7,39.6 | 96.1,39.6 97.8,39.6
S$210
  Bottom 2: 98.2,53 98.2,52 96.6,50.4
S$211
  Bottom 1.5: 72.3,24.1 73.2,24.1 73.6,23.7
  Bottom 2: 63.5,40.4 63.5,41.7 63.2,42 61.8,42 61.7,42.1 61.7,39.9 68.9,32.7 68.9,27.5 72.3,24.1
S$212
  Bottom 1: 60.3,25.6 60.3,33.3 59.7,33.9 59.7,33.6 62.8,30.5
S$213
  Bottom 1: 59.8,28.9 59.8,33.1
S$214
  Bottom 2: 60.4,29 60.4,28.8 54,22.4 54,19.4 54.5,18.9 62,18.9 64.4,21.3 64.4,22.7 62.4,24.7 62.4,30.2 61.3,31.3 61.3,27.6 55.5,21.8 55.5,20.4 61.4,20.4 63,22 63,23.7 61.2,25.5 61.2,25.3 57.2,21.3 60,21.3 61.6,22.9 61.6,23.7 61.4,23.9 61,23.9 58.6,21.5
S$215
  Bottom 1.5: 16.6,7.4 16.6,14.5 19.1,17 19.2,17
  Bottom 2: 19.2,17 19.3,17
S$216
  Bottom 2: 33.7,21.8 33.7,21.2 33.7,20.6
S$217
  Bottom 2: 36.3,20.6 36.3,21.2 36.3,21.7
S$218
  Bottom 2: 38.9,20.6 38.9,21.3 38.9,21.7
S$219
  Bottom 2: 38.8,28.2 38.8,29.4
S$220
  Bottom 1: 21.7,11.8 21.7,12.2 21.8,12.3
  Bottom 1.5: 21.7,7.4 21.7,12.6
  Bottom 2: 21.7,8 21.7,7.4 21.7,6.8 | 21.7,11.8 21.7,12.6 21.7,13.1
S$221
  Bottom 2: 40.8,41.6 41.4,41.6 42,41.6
S$222
  Bottom 2: 47.8,37.6 47.6,37.6
S$223
  Bottom 2: 29.5,28.8 27.7,28.8
S$224
  Bottom 1: 45,16.4 49.5,20.9 51.1,20.9
  Bottom 1.5: 51.1,24 51.1,20.9 51,20.8 49.6,20.8 45.3,16.5
  Bottom 2: 51.1,20.9 51.1,20.8
S$225
  Bottom 2: 48.8,65.4 48.8,64.4 48.8,63.8
S$226
  Bottom 0.5: 23.7,54.1 24.5,54.1 28.6,50 28.6,47.9 25.3,44.6 22.7,44.6 15.8,51.5 13.1,51.5 9.8,54.8 9.8,64.8 11.2,66.2 14.5,66.2 16.5,68.2 16.5,74.1 17,74.6 98.9,74.6 99.6,73.9 99.6,49.2 99.1,48.7 95.9,48.7 95,49.6 95,50.9 95.3,51.2 95.3,59.1 90.5,63.9 90.5,69.8 88.6,71.7 80.6,71.7 78.7,73.6
S$227
  Bottom 2: 17.5,43.2 17.6,43.2
S$228
  Bottom 1.5: 20.4,33.3 20.4,33.8 16.9,37.3 13.7,37.3 11.5,39.5
S$229
  Bottom 1: 9,31.5 9.3,31.2 13.9,31.2 16.7,28.4 16.7,28.3 16.9,28.5 17.6,28.5 14,32.1 7.6,32.1 7.7,32.2 7.7,32.8 14.4,32.8 18.5,28.7 17.8,28 16.8,28 14.3,25.5 14.3,20.9 14.7,21.3 14.7,24.8 16.7,26.8 19.2,26.8 19.9,27.5 19.9,28.3 14.5,33.7 7.2,33.7 8.7,32.2 8.7,30.9 | 24.5,19.9 24.4,19.8 24.4,19.3 24.4,12.6 | 26.9,20.1 24.4,20.1 24.2,20.1
  Bottom 1.5: 24.4,20.1 24.4,23.2 19.6,28 16.8,28 13.6,28 13.5,27.9
  Bottom 2: 24.4,20.7 24.4,20.1 24.4,19.3
S$230
  Bottom 2: 11.3,17.4 11.3,17.3
S$231
  Bottom 1: 24.3,14.8 27.8,14.8
  Bottom 1.5: 25.9,20.2 24.6,20.2 24.3,19.9 24.3,14.8 24.3,12.5
  Bottom 2: 24.3,12.1 24.3,12.5 24.3,13.3
S$232
  Bottom 1.5: 40.9,9.7 39.9,9.7 38.2,8
S$233
  Bottom 1.5: 62.7,9.2 57.5,14.4 29.5,14.4 29.1,14.8 28.3,14.8
S$234
  Bottom 1: 29.7,39.1 32.5,39.1 32.6,39
S$235
  Bottom 1.5: 27.6,31.5 29.5,31.5
S$236
  Bottom 2: 83.9,43 83.9,43.9 83.9,44.7
S$237
  Bottom 2: 79.1,43 79.1,44 79.1,44.8
S$238
  Bottom 2: 75.2,40.2 75.2,40.4
S$239
  Bottom 2: 69,42 69.1,42
S$240
  Bottom 2.5: 66.2,46.4 66.3,46.4
S$241
  Bottom 2: 71.5,45.5 71.6,45.5
S$242
  Bottom 2: 72.6,48.7 72.6,48.8
S$243
  Bottom 2: 89.2,58.8 89.2,58.9
S$244
  Bottom 2: 91.8,58.8 91.8,58.7
S$245
  Bottom 2: 88.2,66.4 88.2,66.5
S$246
  Bottom 2: 81.2,66.4 81.2,66.3
S$247
  Bottom 2: 74.7,66.6 74.7,66.5
S$248
  Bottom 2: 77.5,66.8 77.5,66.7
S$249
  Bottom 2: 88.1,69.7 88.1,69.5
S$250
  Bottom 2: 75.6,25.9 75.5,25.9
S$251
  Bottom 2: 12.2,55.2 11.8,55.2 11.4,54.8 11.4,54.6 13.5,52.5 16.3,52.5 23.2,45.6 24.8,45.6 27.5,48.3 27.5,49.7 25.1,52.1 25.1,52 24.1,51 24.3,51 26,49.3 26,48.9 24.1,47 23.3,47 23,47.3 23,47.6 25,49.6
S$252
  Bottom 2: 14.9,28.6 15,28.6 15,28.4 13.8,29.6 13.8,29.8 13.6,30 10.6,30 10.6,28.4 10.7,28.5 12.6,28.5 14.4,26.7 14.4,25.6
S$253
  Bottom 1: 12.7,29.3 14.6,27.4 15.9,27.4 15.8,27.5 15.8,28 | 15.8,28 15.9,28.1 | 15.8,28.2 15.8,28
  Bottom 1.5: 16,28 15.8,28.2
S$254
  Bottom 1.5: 9.7,36.1 12.7,36.1 13.8,37.2
S$255
  Bottom 2: 29.6,38.9 32,38.9
S$256
  Bottom 1.5: 14.7,30.1 17.6,33
S$257
  Bottom 1.5: 39.7,5.9 39.2,5.9 37.8,7.3
S$258
  Bottom 1: 16.1,20 13,20 12.8,20.2 16.3,20.2 16.5,20 16.5,20.4 15.3,21.6 15.3,20.8
S$259
  Bottom 2: 17.6,33.1 17.5,33
S$260
  Bottom 2: 20.5,33.1 20.5,33.2
S$261
  Bottom 2: 17.7,23 17.4,23
S$262
  Bottom 1.5: 19.1,22.3 19.1,20.1 | 19.1,22.3 19.1,23.5 | 20.5,23.1 20.4,23.1 19.9,23.1 19.1,22.3
  Bottom 2: 18.8,23.2 18.7,23.2 18.6,23.3 20.4,23.3 20.5,23.2 | 20.5,23.2 20.4,23.1 | 20.5,23.2 17.7,23.2 17.6,23.1
S$263
  Bottom 2: 29.5,4.4 29.6,4.4
S$264
  Bottom 2: 22,4.1 22,4.2
S$265
  Bottom 1.5: 26.8,12.3 26.8,9.9 26,9.1 26,3.1 24.5,1.6 17.1,1.6 14.1,4.6 14.1,16.5 15.1,17.5 11.3,17.5 11.2,17.5
  Bottom 2: 11.3,17.5 14.9,17.5 15.1,17.3
S$266
  Bottom 2: 24.2,51.6 24.2,62.3 21.5,65 21.5,70.9 24.4,73.8 24.7,73.8 24.6,73.7 17.6,73.7 17.5,73.6 17.5,67.7 15,65.2 11.6,65.2 10.8,64.4 10.8,55.2
S$267
  Bottom 2: 27.5,43.6 27.4,43.6
S$268
  Bottom 2: 14.6,45.9 14.6,46.1
S$269
  Bottom 2: 12.6,48.5 12.6,48.6
S$270
  Bottom 2: 7.4,48.6 7.4,48.5
S$271
  Bottom 0.5: 11.3,35.9 12.5,35.9 12.8,35.6 18.3,35.6
S$272
  Bottom 1.5: 12.7,37.2 12.2,37.2 11.3,37.2
  Bottom 2: 10.1,40.5 9.3,41.3 9.3,43.3 9.4,43.4 12.6,43.4 17.5,38.5 17.5,36.7 17.3,36.5 12.9,36.5 12.2,37.2 12.2,37.5 13,38.3 15.7,38.3 15.8,38.2 15.6,38.2 11.9,41.9 10.8,41.9 10.8,41.4 12.7,39.5
S$273
  Bottom 2: 51,23.9 51,23.8
S$274
  Bottom 2: 51.2,26.6 51.1,26.6
S$275
  Bottom 2: 53.8,36.1 53.7,36.2
S$276
  Bottom 1.27: 25.2,35.6 24.8,36 22.6,38.2
  Bottom 1.3: 33.6,28.8 33.6,30.9 31.6,32.9 31.5,32.9 31,33.4 27.4,33.4 24.8,36
S$277
  Bottom 1.5: 63.3,40.8 63.8,40.8 63.9,40.9 63.9,44.8 63.3,45.4
S$278
  Bottom 1.5: 62.9,42.3 62.9,43.8 63.2,44.1
S$279
  Bottom 1.5: 62.6,41.2 61.5,41.2 61.4,41.1 61.4,44.1 62.2,44.9 | 62.2,42.1 62.2,44.9 | 62.2,44.9 63,45.7 63.3,46 63.3,47.5 64.8,49 68.1,49 69.2,47.9
S$280
  Bottom 1.5: 32.1,35.6 28.6,35.6 25.2,39 25.2,42.2 23.5,43.9 23.5,45 23.6,45.1
S$281
  Bottom 1.3: 27.6,28.9 29.9,28.9
S$282
  Bottom 2: 29.4,31.3 27.7,31.3

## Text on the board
Bottom: Multiplu | By Marian | Iul-2013 | Afisaj digital
Dimension: Vca1 | 1 | 3 | 5 | 7 | 9 | 11 | 13 | 15 | 2 | 4 | 6 | 8 | 10 | 12 | 14 | 16 | Vca1 | Rs | Gnd | Trf | Vca2 | Vca2 | Ret | VccIn | VccOut
tOrigins: 100mm | 75mm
